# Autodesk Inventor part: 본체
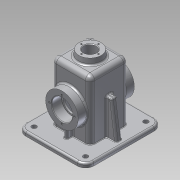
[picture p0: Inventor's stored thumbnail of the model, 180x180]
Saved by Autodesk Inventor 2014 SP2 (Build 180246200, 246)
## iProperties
Created: 2016-08
Part Number: 본체
Material: 알루미늄 6061
Document SubType Name: Modeling
Designer: user
Density: 2.71 g/cm^3
Appearance: 알루미늄 - 평지
Mass: 796.088 g
Surface Area: 911.213 cm^2
Volume: 293.76 cm^3
Author: user
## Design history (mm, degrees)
sketch "스케치1"
  geometry: L1 (-57.5, 65)-(57.5, 65); L2 (57.5, 65)-(57.5, -65); L3 (57.5, -65)-(-57.5, -65); L4 (-57.5, -65)-(-57.5, 65); L5 (-57.5, 65)-(57.5, -65); L6 (57.5, 65)-(-57.5, -65); 1 further point
  constraints: 12 end point, 2 midpoint, 2 parallel, 1 horizontal, 1 perpendicular
  dimensions: "d0" = 115 distance of L2.end L3.end; "d1" = 130 distance of L1.end L2.end
extrude "돌출1" new body sketch "스케치1" distance "d2" = 10; taper "d3" = 0 deg
node "작업 평면1"
sketch "스케치2"
  geometry: L1 (-32.5, -32.5)-(32.5, -32.5); L2 (32.5, -32.5)-(32.5, 32.5); L3 (32.5, 32.5)-(-32.5, 32.5); L4 (-32.5, 32.5)-(-32.5, -32.5); L5 (-32.5, -32.5)-(32.5, 32.5); L6 (32.5, -32.5)-(-32.5, 32.5); 1 further point
  constraints: 12 end point, 2 midpoint, 2 parallel, 1 horizontal, 1 perpendicular
  dimensions: "d5" = 65 distance of L3.end L2.end; "d6" = 65 distance of L2.end L1.end
extrude "돌출2" join sketch "스케치2" stored distance "d7" = 10; taper "d8" = 0 deg
sketch "스케치3"
  geometry: L1 (27.5, 27.5)-(-27.5, 27.5); L2 (-27.5, 27.5)-(-27.5, -27.5); L3 (-27.5, -27.5)-(27.5, -27.5); L4 (27.5, -27.5)-(27.5, 27.5); L5 (27.5, 27.5)-(-27.5, -27.5); L6 (-27.5, 27.5)-(27.5, -27.5); 1 further point
  constraints: 12 end point, 2 midpoint, 2 parallel, 1 horizontal, 1 perpendicular
  dimensions: "d9" = 55 distance of L3.end L2.end; "d10" = 55 distance of L2.end L1.end
extrude "돌출3" cut sketch "스케치3" distance "d11" = 105; taper "d12" = 0 deg
sketch "스케치4"
  geometry: L1 (-52.5, -60)-(52.5, -60); L2 (52.5, -60)-(52.5, 60); L3 (52.5, 60)-(-52.5, 60); L4 (-52.5, 60)-(-52.5, -60); L5 (-52.5, -60)-(52.5, 60); L6 (52.5, -60)-(-52.5, 60); L7 (57.5, -65)-(-57.5, -65) reference; L8 (57.5, 65)-(57.5, -65) reference; L9 (-57.5, 65)-(57.5, 65); L10 (57.5, 65)-(57.5, -65); L11 (57.5, -65)-(-57.5, -65); L12 (-57.5, -65)-(-57.5, 65); L13 (-57.5, 65)-(57.5, -65); L14 (57.5, 65)-(-57.5, -65); 1 further point
  constraints: 24 end point, 4 midpoint, 4 parallel, 2 horizontal, 2 perpendicular
  dimensions: "d13" = 105 distance of L3.end L2.end; "d14" = 120 distance of L2.end L1.end
extrude "돌출4" cut sketch "스케치4" distance "d15" = 3; taper "d16" = 0 deg
sketch "스케치6"
  geometry: C1 r 20 at (0, 0); 1 further point
  constraints: 1 centre point, 1 coincident
  dimensions: "d19" = 40 diameter of C1
extrude "돌출5" join sketch "스케치6" distance "d20" = 10; taper "d21" = -7 deg
hole "구멍1" diameter "d24" = 21; stored, may be unused: countersink angle "d28" = 90 deg, drill point angle "d30" = 0 deg; dims "d22" = 10, "d23" = 10, "d25" = 6, "d26" = 4, "d27" = 2, "d29" = 8
sketch "스케치7"
  geometry: L1 (0, 14.5)-(0, -14.5); L2 (14.5, 0)-(-14.5, 0); A1 r 14.5 centre (0, 0) between (0, 14.5) and (0, -14.5); 6 further points
  constraints: 6 coincident, 4 end point, 4 point on circle, 2 midpoint, 1 centre point, 1 perpendicular, 1 vertical
  dimensions: "d31" = 29 diameter of A1
hole "구멍2" sketch "스케치7" at (0, 14.5), (-14.5, 0), (0, -14.5), (14.5, 0) diameter "d32" = 2.459; stored, may be unused: countersink angle "d36" = 90 deg, drill point angle "d38" = 118 deg; dims "d33" = 7, "d34" = 4, "d35" = 2, "d37" = 9
node "작업 평면3"
sketch "스케치8"
  geometry: L1 (27.5, 0)-(-27.5, 0) reference; C1 r 27.5 at (0, 55); 2 further points
  constraints: 1 centre point, 1 midpoint, 1 vertical alignment
  dimensions: "d41" = 55 diameter of C1; "d140" = 55 distance from line of C1.centre L1
extrude "돌출6" join sketch "스케치8" stored distance "d42" = 10; taper "d43" = 0 deg
hole "구멍3" diameter "d46" = 30; stored, may be unused: countersink angle "d50" = 90 deg, drill point angle "d52" = 0 deg; dims "d44" = 10, "d45" = 10, "d47" = 7, "d48" = 35, "d49" = 17, "d51" = 9
sketch "스케치9"
  geometry: L1 (21, 55)-(-21, 55); L2 (0, 76)-(0, 34); C1 r 27.5 at (0, 55) reference; A1 r 21 centre (0, 55) between (21, 55) and (-21, 55); 7 further points
  constraints: 7 coincident, 4 end point, 4 point on circle, 2 midpoint, 1 centre point, 1 horizontal, 1 perpendicular
  dimensions: "d53" = 42 diameter of A1
hole "구멍4" sketch "스케치9" at (0, 76), (21, 55), (0, 34), (-21, 55) diameter "d54" = 3.242; stored, may be unused: countersink angle "d58" = 90 deg, drill point angle "d60" = 118 deg; dims "d55" = 8, "d56" = 35, "d57" = 17, "d59" = 10
sketch "스케치10"
  geometry: L1 (65, 10)-(-65, 10) reference; L2 (-32.5, 110)-(-32.5, 10) reference; L3 (-47.5, 27.5)-(-32.5, 27.5) reference; L4 (-42.5, 10)-(-42.5, 27.5); L5 (-27.5, 0)-(-27.5, 105) reference; 2 further points
  constraints: 2 end point, 2 point on line, 1 perpendicular
  dimensions: "d61" = 15 distance between parallel lines of L4 L5
feature "리브1" sketch "스케치10" dims "d62" = 1, "d63" = 6, "d64" = 0, "d65" = 0, "d66" = 1, "d67" = 1
fillet "모깎기1" dims "d68" = 14
fillet "모깎기2" dims "d69" = 9
fillet "모깎기3" dims "d70" = 3
fillet "모깎기4" dims "d71" = 8
fillet "모깎기5" dims "d72" = 8
sketch "스케치11"
  geometry: L1 (43.5, 10)-(54.5, 10) reference; L2 (43.5, 10)-(-43.5, 10) reference; L3 (32.5, 10)-(32.5, 102) reference; L4 (57.5, 3)-(57.5, 7) reference; L5 (49.5, 10)-(41.068, 70); L6 (41.068, 70)-(32.5, 70); A1 r 3 centre (54.5, 7) between (57.5, 7) and (54.5, 10) reference; 1 further point
  constraints: 4 end point, 2 point on line, 1 perpendicular
  dimensions: "d73" = 8 deg angle of L5 L4; "d74" = 8 distance from line of L5.start L4; "d75" = 70 vertical distance of L5.end point (0, 0)
feature "리브2" sketch "스케치11" dims "d76" = 1, "d77" = 10, "d78" = 0, "d79" = 0, "d80" = 1, "d81" = 1
hole "구멍5" diameter "d84" = 8; stored, may be unused: countersink angle "d88" = 90 deg, drill point angle "d90" = 118 deg; dims "d82" = 10, "d83" = 10, "d85" = 8, "d86" = 35, "d87" = 17, "d89" = 10
hole "구멍6" diameter "d93" = 8; stored, may be unused: countersink angle "d97" = 90 deg, drill point angle "d99" = 118 deg; dims "d91" = 10, "d92" = 10, "d94" = 8, "d95" = 35, "d96" = 17, "d98" = 10
hole "구멍7" diameter "d102" = 8; stored, may be unused: countersink angle "d106" = 90 deg, drill point angle "d108" = 118 deg; dims "d100" = 10, "d101" = 10, "d103" = 8, "d104" = 35, "d105" = 17, "d107" = 10
hole "구멍8" diameter "d111" = 8; stored, may be unused: countersink angle "d115" = 90 deg, drill point angle "d117" = 118 deg; dims "d109" = 10, "d110" = 10, "d112" = 8, "d113" = 35, "d114" = 17, "d116" = 10
fillet "모깎기6" dims "d118" = 3
fillet "모깎기7" dims "d119" = 3
fillet "모깎기8" dims "d120" = 3
fillet "모깎기9" dims "d122" = 3
fillet "모깎기10" dims "d123" = 3
fillet "모깎기11" dims "d124" = 1
fillet "모깎기12" dims "d125" = 3
fillet "모깎기13" dims "d126" = 3
chamfer "모따기1" distance "d127" = 1; stored, may be unused: second distance "d128" = 2, angle "d129" = 45 deg
chamfer "모따기2" distance "d130" = 1; stored, may be unused: second distance "d131" = 2, angle "d132" = 45 deg
fillet "모깎기14" dims "d133" = 0.3
fillet "모깎기15" dims "d134" = 3
fillet "모깎기16" dims "d135" = 3
sketch "스케치12"
  geometry: L1 (43.272, -18)-(5.728, -18) reference; L2 (57, 0)-(57, 91) reference; 2 further points
  constraints: 1 other
  dimensions: "d136" = 26 distance from line of L1 point (24.5, 8); "d137" = 32.5 distance from line of point (24.5, 8) L2
feature "엠보싱1" sketch "스케치12" dims "d9" = 55, "d10" = 55, "d138" = 0.5, "d139" = 0
node "솔리드1"
mirror "대칭1"
mirror "대칭2"
other parameters: "d39" = -47.5
